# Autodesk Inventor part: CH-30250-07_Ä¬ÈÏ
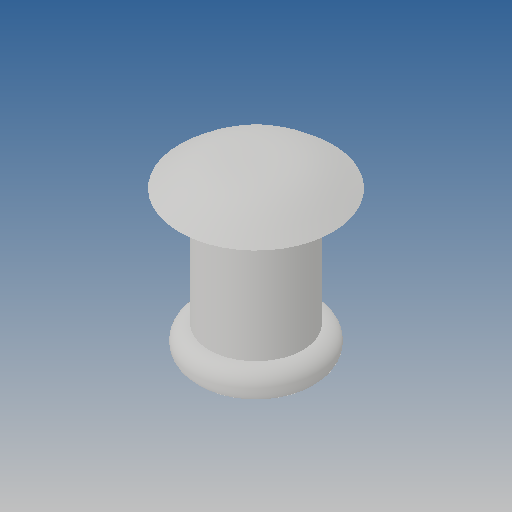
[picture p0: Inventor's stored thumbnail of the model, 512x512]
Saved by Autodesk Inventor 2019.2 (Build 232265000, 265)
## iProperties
Created: 2010-06
Part Number: CH-30250-07_Ä¬ÈÏ
Material: Ogólny
Document SubType Name: Modeling
Designer: CADENGINEERING4
Density: 1 g/cm^3
Appearance: Domyślna
Author: CADENGINEERING4
Revision Number: ÈÎºÎ
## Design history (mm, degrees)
feature "NONE"
node "Bryła1"
